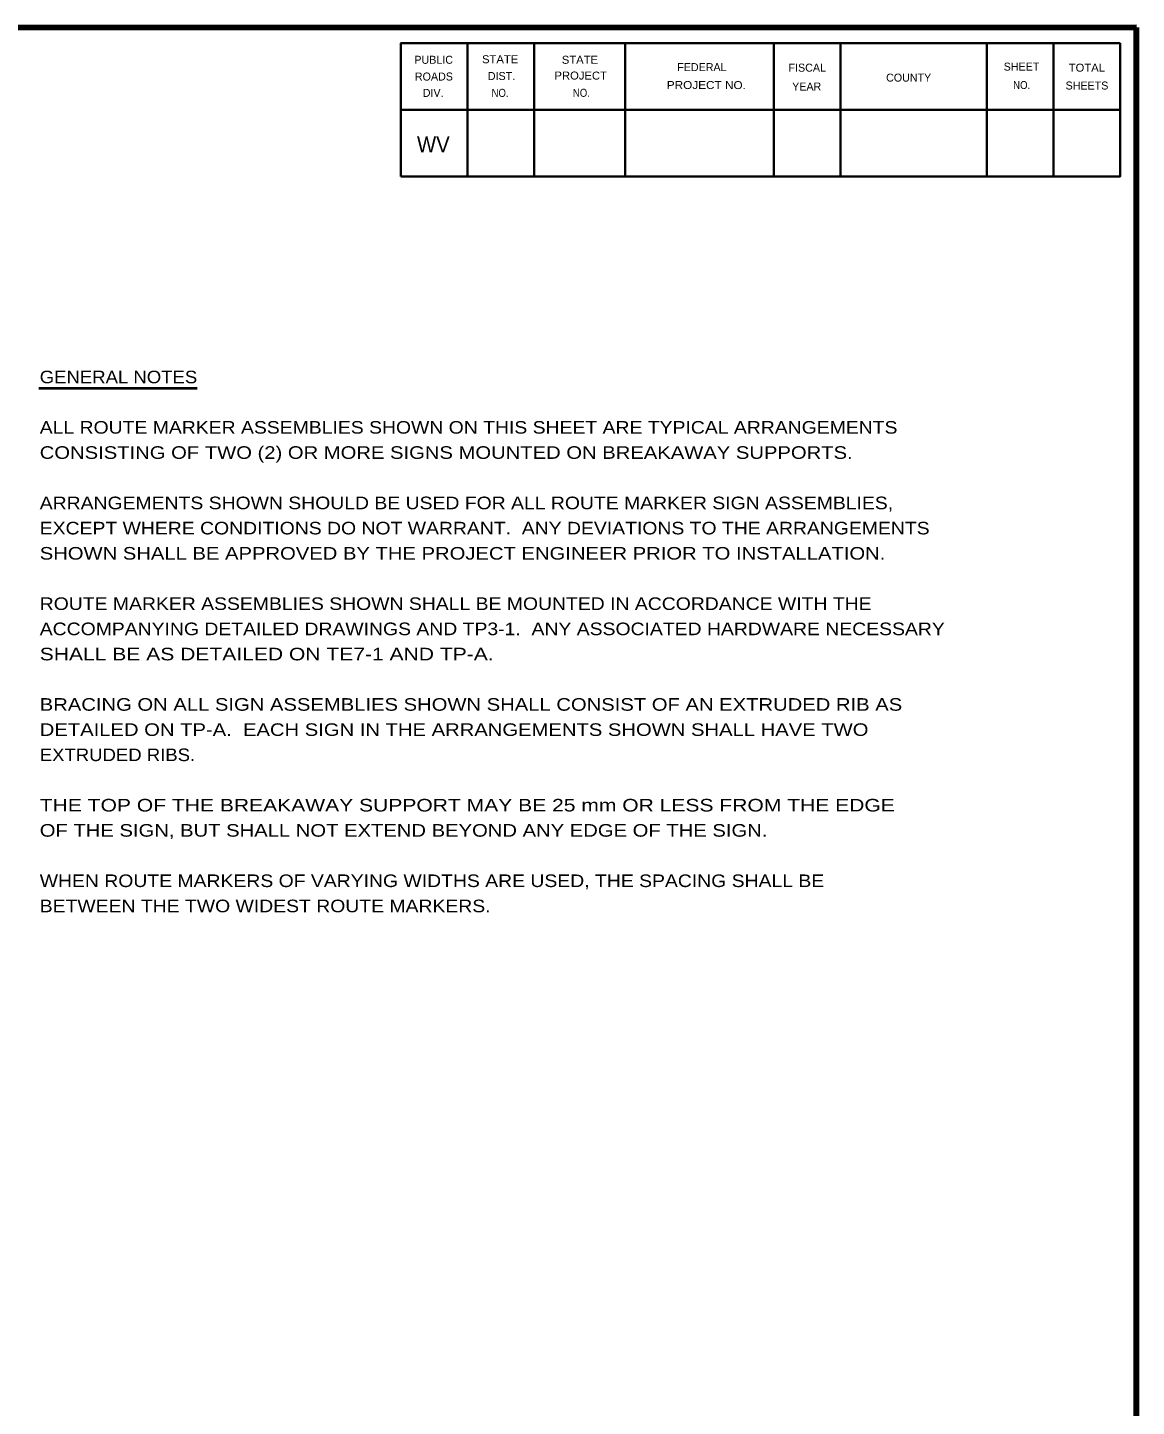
# Model space of a CAD drawing. Extents: x 851 to 1706, y -23 to 521.
# Drawn here: x 1488.4 to 1699.7, y 251.5 to 514.3 of the extents above; entities that cross this region are included whole.
import ezdxf

# ---------------------------------------------------------------- set-up
doc = ezdxf.new("R2010")
doc.units = 0
doc.layers.add('1', color=7, linetype='Continuous', lineweight=35)
doc.layers.add('61', color=7, linetype='Continuous', lineweight=35)

msp = doc.modelspace()

# ---------------------------------------------------------------- linework, layer by layer
at = {"layer": '1', "lineweight": 158}
msp.add_line((1699.744, -11.848), (1699.744, 514.252), dxfattribs=at)
at = {"layer": '1', "lineweight": 13}
msp.add_line((1699.744, -11.848), (1699.744, 514.252), dxfattribs=at)
at = {"layer": '1', "lineweight": 40}
msp.add_line((1490.597, 445.557), (1520.743, 445.557), dxfattribs=at)
at = {"layer": '1', "lineweight": 158}
msp.add_lwpolyline([(1699.744, 514.252), (908.044, 514.152), (908.144, -11.848)], dxfattribs=at)
at = {"layer": '61'}
for p, q in [((1572.244, 511.252), (1572.244, 485.852)), ((1584.944, 511.252), (1584.944, 485.852)), ((1602.344, 511.252), (1602.344, 485.852)), ((1630.644, 511.252), (1630.644, 485.852)), ((1643.344, 511.252), (1643.344, 485.852)), ((1671.244, 511.252), (1671.244, 485.852)), ((1683.944, 511.252), (1683.944, 485.852)), ((1696.644, 498.552), (1559.544, 498.552))]:
    msp.add_line(p, q, dxfattribs=at)
for points in [[(1696.644, 511.252), (1559.544, 511.252), (1559.544, 485.852)], [(1696.644, 511.252), (1696.644, 485.852), (1559.544, 485.852)]]:
    msp.add_lwpolyline(points, dxfattribs=at)

# ---------------------------------------------------------------- texts
at = {"layer": '1'}
for s, height, width, p in [('WV', 3.048, 0.95, (1562.644, 490.452)), ('GENERAL NOTES', 2.4, 1.1, (1490.755, 446.469)), ('ALL ROUTE MARKER ASSEMBLIES SHOWN ON THIS SHEET ARE TYPICAL ARRANGEMENTS', 2.4, 1.15, (1490.755, 436.869)), ('CONSISTING OF TWO (2) OR MORE SIGNS MOUNTED ON BREAKAWAY SUPPORTS.', 2.4, 1.2, (1490.755, 432.069)), ('ARRANGEMENTS SHOWN SHOULD BE USED FOR ALL ROUTE MARKER SIGN ASSEMBLIES,', 2.4, 1.15, (1490.755, 422.469)), ('EXCEPT WHERE CONDITIONS DO NOT WARRANT.  ANY DEVIATIONS TO THE ARRANGEMENTS ', 2.4, 1.15, (1490.755, 417.669)), ('SHOWN SHALL BE APPROVED BY THE PROJECT ENGINEER PRIOR TO INSTALLATION.', 2.4, 1.2, (1490.755, 412.869)), ('ROUTE MARKER ASSEMBLIES SHOWN SHALL BE MOUNTED IN ACCORDANCE WITH THE', 2.4, 1.15, (1490.755, 403.269)), ('ACCOMPANYING DETAILED DRAWINGS AND TP3-1.  ANY ASSOCIATED HARDWARE NECESSARY', 2.4, 1.15, (1490.755, 398.469)), ('SHALL BE AS DETAILED ON TE7-1 AND TP-A.', 2.4, 1.25, (1490.755, 393.669)), ('BRACING ON ALL SIGN ASSEMBLIES SHOWN SHALL CONSIST OF AN EXTRUDED RIB AS', 2.4, 1.2, (1490.755, 384.069)), ('DETAILED ON TP-A.  EACH SIGN IN THE ARRANGEMENTS SHOWN SHALL HAVE TWO', 2.4, 1.2, (1490.755, 379.269)), ('EXTRUDED RIBS. ', 2.4, 1.1, (1490.755, 374.469)), ('THE TOP OF THE BREAKAWAY SUPPORT MAY BE 25 mm OR LESS FROM THE EDGE', 2.4, 1.25, (1490.755, 364.869)), ('OF THE SIGN, BUT SHALL NOT EXTEND BEYOND ANY EDGE OF THE SIGN.', 2.4, 1.2, (1490.755, 360.069)), ('WHEN ROUTE MARKERS OF VARYING WIDTHS ARE USED, THE SPACING SHALL BE', 2.4, 1.15, (1490.755, 350.469)), ('BETWEEN THE TWO WIDEST ROUTE MARKERS.', 2.4, 1.15, (1490.755, 345.669))]:
    msp.add_text(s, height=height, dxfattribs=dict(at, width=width)).set_placement(p)
at = {"layer": '61'}
for s, height, rotation, p in [('PUBLIC', 1.525, 0.033, (1562.144, 507.352)), ('FEDERAL', 1.523, 0.007, (1612.244, 505.952)), ('FISCAL', 1.525, 359.942, (1633.444, 505.852)), ('SHEET', 1.525, 0.059, (1674.444, 506.052)), ('ROADS', 1.525, 0.124, (1562.244, 504.152)), ('DIST.', 1.525, 0.056, (1576.144, 504.252)), ('COUNTY', 1.523, 0.069, (1652.044, 503.952)), ('DIV.', 1.525, 359.932, (1563.744, 501.052)), ('YEAR', 1.523, 0.105, (1634.144, 502.252)), ('SHEETS', 1.523, 359.959, (1686.244, 502.452))]:
    msp.add_text(s, height=height, rotation=rotation, dxfattribs=at).set_placement(p)
for s, rotation, width, p in [('STATE', 0.059, 1.05, (1575.044, 507.452)), ('STATE', 0.059, 1.05, (1590.244, 507.352)), ('TOTAL', 359.926, 1.05, (1686.844, 505.852)), ('PROJECT', 359.908, 1.05, (1588.844, 504.352)), ('NO.', 359.852, 0.9, (1576.844, 501.052)), ('NO.', 0.225, 0.9, (1592.344, 501.052)), ('PROJECT NO.', 359.922, 1.1, (1610.244, 502.552)), ('NO.', 359.852, 0.9, (1676.244, 502.552))]:
    msp.add_text(s, height=1.525, rotation=rotation, dxfattribs=dict(at, width=width)).set_placement(p)

doc.saveas('drawing.dxf')
